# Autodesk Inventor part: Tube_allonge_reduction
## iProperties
Shininess: 64.0
Length Units: 11269
Angle Units: 11279
Time Units: 11290
Mass Units: 11283
Length Display Precision: 3
Angle Display Precision: 2
Compacted: True
Part Number: Tube_allonge_reduction
Document SubType Name: Modeling
Created: 2008-04
Material: Par défaut
Designer: plup
Density: 0.0
Volumn: 0.0
Area: 0.0
PropertySet Name: Model Information
Control State: 0
Master: False
Checked Out: False
MATIERE_PIECE: X2CrNi 18-11
OBSERVATIONS: Tube Ø..
DESIGNATION: Manchon
Author: plup
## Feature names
1. Extrusion1
